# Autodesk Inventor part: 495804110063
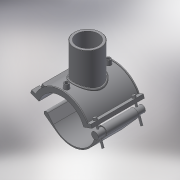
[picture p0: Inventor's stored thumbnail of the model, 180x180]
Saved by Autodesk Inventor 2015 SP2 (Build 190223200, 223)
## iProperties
Created: 2017-07
Part Number: 495804110063
Material: Generic
Description: PLASSON BRANCH SADDLE 110-63
Document SubType Name: Modeling
Designer: KIM
Density: 1 g/cm^3
Appearance: Default
Author: KIM
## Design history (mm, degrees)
derived "495804.ipt"
feature "Solid1::495804.ipt"
feature "Solid2::495804.ipt"
tag "TaggingFeature1"
body "Solid1"
body "Solid2"
other parameters: "d2" = 148, "d3" = 27.5, "d4" = 118, "d5" = 0, "d6" = 0.1, "d8" = 0, "d19" = 6, "d20" = 6, "d21" = 70.8, "d23" = 0, "d24" = 35.4, "d26" = 0, "d27" = 3, "d28" = 3, "d29" = 3, "d30" = 36.66667, "d31" = 6, "d32" = 0, "d33" = 0, "d34" = 0.6, "d40" = 66.56, "d41" = 69.3, "d43" = 0, "d45" = 0, "d47" = 158, "d48" = 63, "d50" = 0, "d70" = 15, "d72" = 0, "d73" = 6, "d75" = 5, "d76" = 0, "d77" = 5.5, "d78" = 85, "d79" = 15, "d80" = 47.2, "d82" = 5 deg, "d84" = 4, "d85" = 14, "d86" = 0, "d87" = 3, "d88" = 0, "d89" = 1, "d90" = 1, "d91" = 94.4, "d92" = 0, "d93" = 0.5, "d94" = 57.89474, "d96" = 130.56, "d97" = 2.36, "d98" = 0, "d102" = 1.89, "d103" = 50.4, "d105" = 0, "d109" = -31.33333, "d117" = 0.63, "d120" = 140 deg, "d121" = 24.228, "d122" = 20 deg, "d123" = 256, "d124" = 76.8, "d126" = 0, "d143" = 115.5, "d150" = 19.8, "d159" = 3.6, "d161" = 2.75, "d162" = 70.8, "d163" = 0, "d167" = 22, "d168" = 58.18182, "d173" = 1, "d175" = 55, "d176" = 20 deg, "d177" = 7.7, "d178" = 18, "d180" = 0, "d185" = 38.35, "d186" = 38.35, "d187" = 64, "d188" = 5.4, "d189" = 7.7, "d190" = 0, "d191" = 96, "d200" = 9, "d202" = 0, "d216" = 106.2, "d217" = 0, "d221" = 43.66, "d222" = 7.7, "d223" = 4.62, "d224" = 55, "d225" = 4.62, "d227" = 15.84, "d230" = 68.2, "d236" = 20 deg, "d237" = 71, "d238" = 20 deg, "d239" = 7.7, "B_" = 148, "H_" = 94, "L_" = 118, "d_t" = 6, "d_1" = 63, "H_1" = 85, "d1" = 128, "d148" = 2.75, "d160" = 2.75
